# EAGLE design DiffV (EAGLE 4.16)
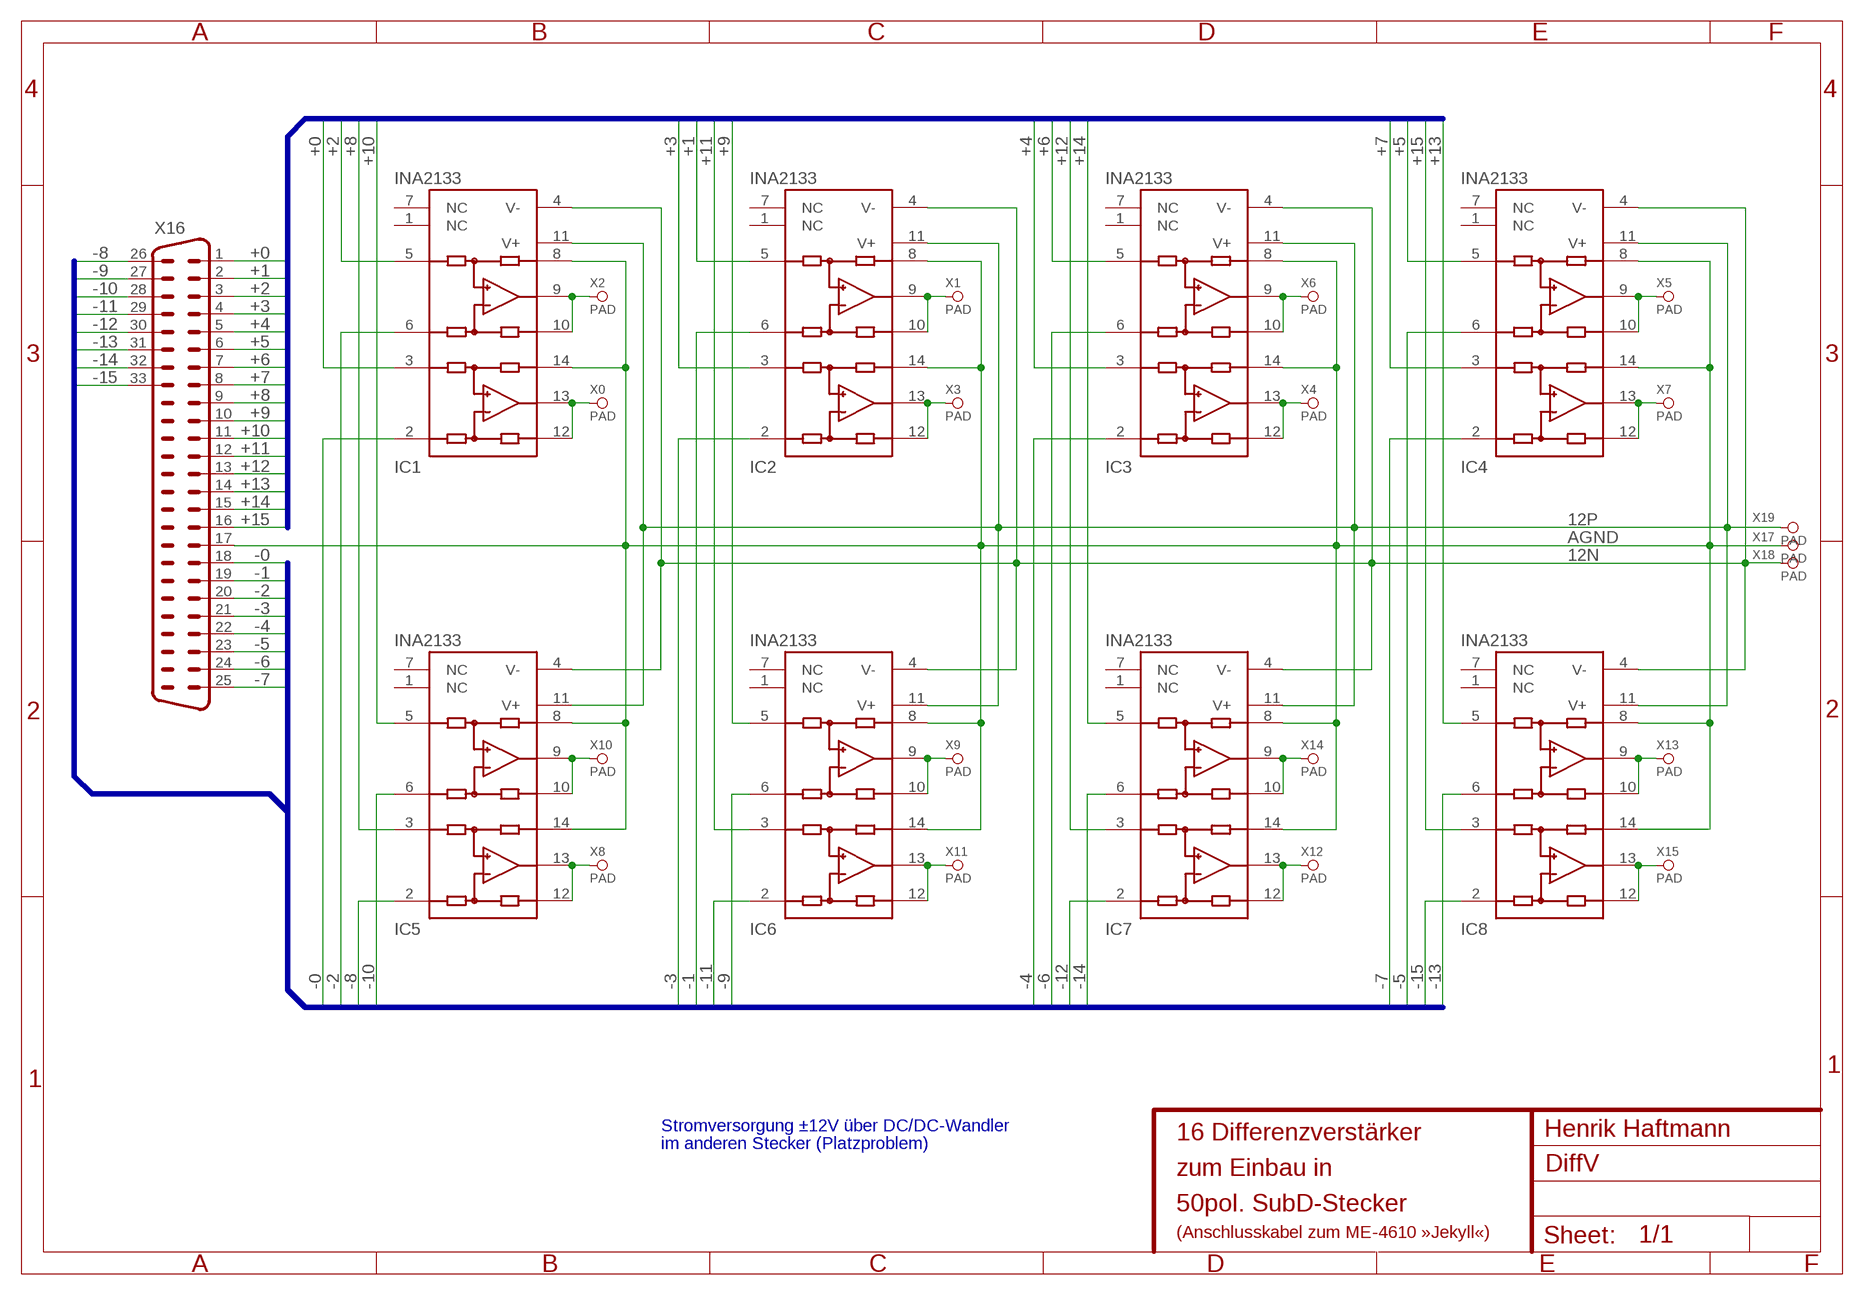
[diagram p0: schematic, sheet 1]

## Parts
IC1  INA2133  INA2134U  [SO14]
IC2  INA2133  INA2134U  [SO14]
IC3  INA2133  INA2134U  [SO14]
IC4  INA2133  INA2134U  [SO14]
IC5  INA2133  INA2134U  [SO14]
IC6  INA2133  INA2134U  [SO14]
IC7  INA2133  INA2134U  [SO14]
IC8  INA2133  INA2134U  [SO14]
X0  PAD  [PAD]
X1  PAD  [PAD]
X2  PAD  [PAD]
X3  PAD  [PAD]
X4  PAD  [PAD]
X5  PAD  [PAD]
X6  PAD  [PAD]
X7  PAD  [PAD]
X8  PAD  [PAD]
X9  PAD  [PAD]
X10  PAD  [PAD]
X11  PAD  [PAD]
X12  PAD  [PAD]
X13  PAD  [PAD]
X14  PAD  [PAD]
X15  PAD  [PAD]
X16  M50  [M50-33]
X17  PAD  [PAD]
X18  PAD  [PAD]
X19  PAD  [PAD]

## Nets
12N: IC1.4(V-) IC2.4(V-) IC3.4(V-) IC4.4(V-) IC5.4(V-) IC6.4(V-) IC7.4(V-) IC8.4(V-) X18.1
12P: IC1.11(V+) IC2.11(V+) IC3.11(V+) IC4.11(V+) IC5.11(V+) IC6.11(V+) IC7.11(V+) IC8.11(V+) X19.1
+0: IC1.3(+INA) X16.1
+1: IC2.5(+INB) X16.2
+2: IC1.5(+INB) X16.3
+3: IC2.3(+INA) X16.4
+4: IC3.3(+INA) X16.5
+5: IC4.5(+INB) X16.6
+6: IC3.5(+INB) X16.7
+7: IC4.3(+INA) X16.8
+8: IC5.3(+INA) X16.9
+9: IC6.5(+INB) X16.10
+10: IC5.5(+INB) X16.11
+11: IC6.3(+INA) X16.12
+12: IC7.3(+INA) X16.13
+13: IC8.5(+INB) X16.14
+14: IC7.5(+INB) X16.15
+15: IC8.3(+INA) X16.16
-0: IC1.2(-INA) X16.18
-1: IC2.6(-INB) X16.19
-2: IC1.6(-INB) X16.20
-3: IC2.2(-INA) X16.21
-4: IC3.2(-INA) X16.22
-5: IC4.6(-INB) X16.23
-6: IC3.6(-INB) X16.24
-7: IC4.2(-INA) X16.25
-8: IC5.2(-INA) X16.26
-9: IC6.6(-INB) X16.27
-10: IC5.6(-INB) X16.28
-11: IC6.2(-INA) X16.29
-12: IC7.2(-INA) X16.30
-13: IC8.6(-INB) X16.31
-14: IC7.6(-INB) X16.32
-15: IC8.2(-INA) X16.33
AGND: IC1.8(REFB) IC1.14(REFA) IC2.8(REFB) IC2.14(REFA) IC3.8(REFB) IC3.14(REFA) IC4.8(REFB) IC4.14(REFA) IC5.8(REFB) IC5.14(REFA) IC6.8(REFB) IC6.14(REFA) IC7.8(REFB) IC7.14(REFA) IC8.8(REFB) IC8.14(REFA) X16.17 X17.1
N$5: IC1.9(OUTB) IC1.10(SENSEB) X2.1
N$6: IC1.12(SENSEA) IC1.13(OUTA) X0.1
N$7: IC5.12(SENSEA) IC5.13(OUTA) X8.1
N$8: IC5.9(OUTB) IC5.10(SENSEB) X10.1
N$9: IC2.9(OUTB) IC2.10(SENSEB) X1.1
N$10: IC6.9(OUTB) IC6.10(SENSEB) X9.1
N$11: IC6.12(SENSEA) IC6.13(OUTA) X11.1
N$12: IC7.9(OUTB) IC7.10(SENSEB) X14.1
N$13: IC7.12(SENSEA) IC7.13(OUTA) X12.1
N$14: IC8.12(SENSEA) IC8.13(OUTA) X15.1
N$15: IC8.9(OUTB) IC8.10(SENSEB) X13.1
N$16: IC4.12(SENSEA) IC4.13(OUTA) X7.1
N$17: IC4.9(OUTB) IC4.10(SENSEB) X5.1
N$18: IC3.9(OUTB) IC3.10(SENSEB) X6.1
N$19: IC3.12(SENSEA) IC3.13(OUTA) X4.1
N$20: IC2.12(SENSEA) IC2.13(OUTA) X3.1
Unconnected: IC1.1(NC) IC1.7(NC) IC2.1(NC) IC2.7(NC) IC3.1(NC) IC3.7(NC) IC4.1(NC) IC4.7(NC) IC5.1(NC) IC5.7(NC) IC6.1(NC) IC6.7(NC) IC7.1(NC) IC7.7(NC) IC8.1(NC) IC8.7(NC)

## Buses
+[0..15]
-[0..15]

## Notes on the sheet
- Stromversorgung ±12V über DC/DC-Wandler
- 16 Differenzverstärker | Henrik Haftmann
- im anderen Stecker (Platzproblem)
- zum Einbau in
- 50pol. SubD-Stecker
- (Anschlusskabel zum ME-4610 »Jekyll«)

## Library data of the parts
IC1-IC8 = burr-brown:INA2134: Audio Differential Line Receivers 0dB, G=1
X0 X1-X15 X17-X19 = DiffV:PAD
X16 = DiffV:M50: SUB-D

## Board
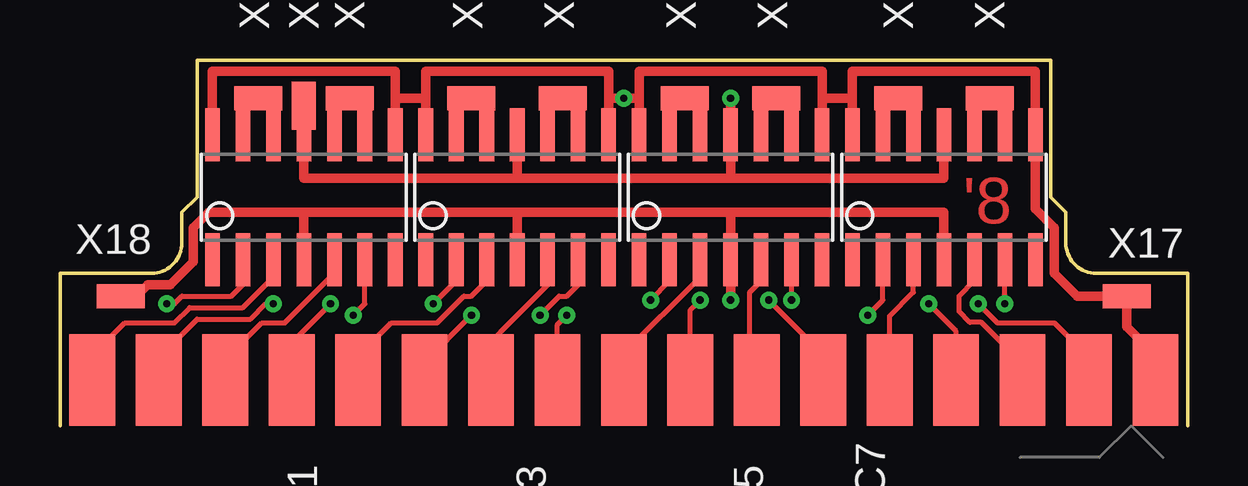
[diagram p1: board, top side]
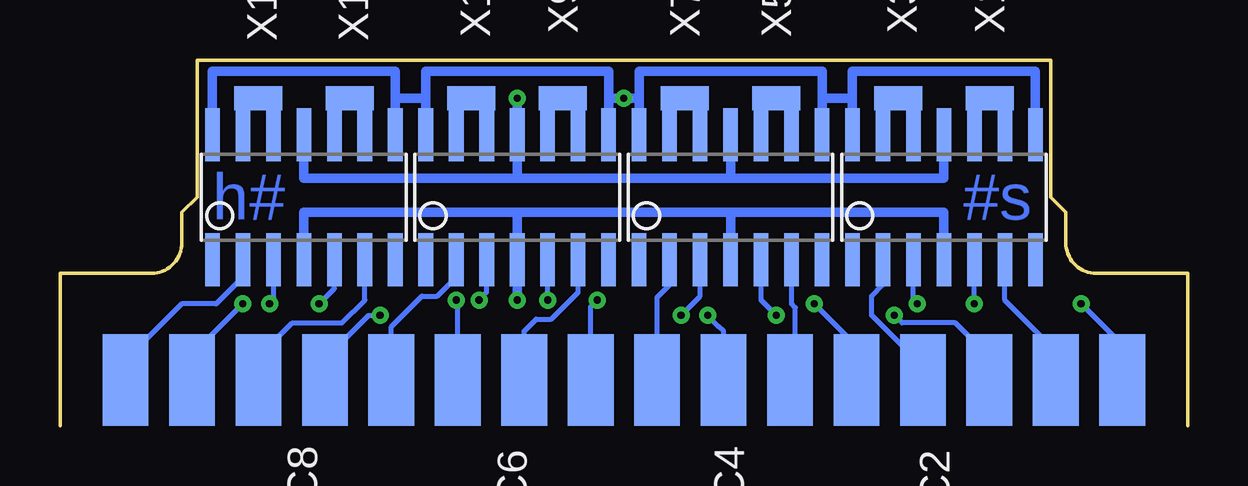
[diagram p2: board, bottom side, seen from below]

Size 46.99 x 15.24 mm. Coordinates in mm from the lower left corner, seen from the top.
Outline: 46.99,0 46.99,6.35 43.18,6.35 arc-90 41.91,7.62 41.91,8.89 41.27,9.53 41.27,15.24 5.71,15.24 5.71,9.53 5.08,8.89 5.08,7.62 arc-90 3.81,6.35 0,6.35 0,0
Copper layers (1*16): Top 0.035mm / dielectric 1.5mm / Bottom 0.035mm
Design rules "Felber": minimum track width 0.2mm, minimum drill 0.3mm, track to track 0.2mm, track to pad 0.2mm, pad to pad 0.2mm, via to via 0.2mm, smd to smd 0mil, copper to edge 0.2mm, drill to drill 0.3mm, minimum pad ring 10mil, minimum via ring 8mil, stop-mask expansion 4mil, vias tented up to drill 0.4mm, thermal gap 10mil

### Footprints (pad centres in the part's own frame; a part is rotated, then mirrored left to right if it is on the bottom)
SO14 = smd 0.61 x 2.21: 1 -3.81,-2.603; 2 -2.54,-2.603; 3 -1.27,-2.603; 4 0,-2.603; 5 1.27,-2.603; 6 2.54,-2.603; 7 3.81,-2.603; 8 3.81,2.603; 9 2.54,2.603; 10 1.27,2.603; 11 0,2.603; 12 -1.27,2.603; 13 -2.54,2.603; 14 -3.81,2.603
PAD = smd 1 x 2: 1 0,0
M50-33 = smd 1.905 x 3.81: 1 22.149,-1.905; 2 19.38,-1.905; 3 16.612,-1.905; 4 13.843,-1.905; 5 11.074,-1.905; 6 8.306,-1.905; 7 5.537,-1.905; 8 2.769,-1.905; 9 0,-1.905; 10 -2.769,-1.905; 11 -5.537,-1.905; 12 -8.306,-1.905; 13 -11.074,-1.905; 14 -13.843,-1.905; 15 -16.612,-1.905; 16 -19.38,-1.905; 17 -22.149,-1.905 | smd 1.905 x 3.81 bottom: 18 20.765,-1.905; 19 17.996,-1.905; 20 15.227,-1.905; 21 12.459,-1.905; 22 9.69,-1.905; 23 6.921,-1.905; 24 4.153,-1.905; 25 1.384,-1.905; 26 -1.384,-1.905; 27 -4.153,-1.905; 28 -6.921,-1.905; 29 -9.69,-1.905; 30 -12.459,-1.905; 31 -15.227,-1.905; 32 -17.996,-1.905; 33 -20.765,-1.905

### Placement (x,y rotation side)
IC1  10.16,9.53 0 top
IC2  10.16,9.53 0 bottom
IC3  19.05,9.53 0 top
IC4  19.05,9.53 0 bottom
IC5  27.94,9.53 0 top
IC6  27.94,9.53 0 bottom
IC7  36.83,9.53 0 top
IC8  36.83,9.53 0 bottom
X0  8.26,13.65 270 top
X1  8.26,13.65 90 bottom
X2  12.07,13.65 270 top
X3  12.07,13.65 90 bottom
X4  17.15,13.65 90 top
X5  17.15,13.65 90 bottom
X6  20.96,13.65 270 top
X7  20.96,13.65 90 bottom
X8  26.04,13.65 270 top
X9  26.03,13.65 270 bottom
X10  29.85,13.65 270 top
X11  29.85,13.65 90 bottom
X12  34.92,13.65 90 top
X13  34.92,13.65 90 bottom
X14  38.73,13.65 270 top
X15  38.73,13.65 90 bottom
X16  23.5,0 180 top
X17  44.45,5.4 270 top
X18  2.54,5.4 270 top
X19  10.16,13.34 0 top

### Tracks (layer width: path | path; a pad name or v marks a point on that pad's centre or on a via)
12N  (via drill 0.3)
  Top 0.4: IC8.4 36.83,8.89 27.94,8.89 | 27.94,8.89 IC6.4 v27.94,5.24 | 19.05,8.89 IC4.4 | 19.05,8.89 27.94,8.89 | 10.16,8.89 IC2.4 | 10.16,8.89 19.05,8.89 | X18.1 3.17,5.4 3.65,5.87 4.6,5.87 5.56,6.83 | 5.56,6.83 | 5.56,6.83 5.56,8.26 6.19,8.89 10.16,8.89
  Bottom 0.2: 27.94,6.99 IC6.4
  Bottom 0.4: IC2.4 10.16,8.89 19.05,8.89 | 19.05,8.89 IC4.4 | 27.94,8.89 27.94,6.99 v27.94,5.24 | 27.94,8.89 19.05,8.89 | IC8.4 36.83,8.89 27.94,8.89
12P  (via drill 0.3)
  Top 0.2: X19.1 | IC2.11 X19.1
  Top 0.4: 19.05,10.32 IC4.11 | 19.05,10.32 10.16,10.32 IC2.11 | 27.94,10.32 19.05,10.32 | 27.94,10.32 36.83,10.32 IC8.11 | v27.94,13.65 IC6.11 27.94,10.32
  Bottom 0.4: 19.05,10.32 IC4.11 | 19.05,10.32 10.16,10.32 IC2.11 | 19.05,10.32 27.94,10.32 | v27.94,13.65 IC6.11 27.94,10.32 | IC8.11 36.83,10.32 27.94,10.32
+0
  Top 0.2: IC1.3 8.89,6.19 7.62,4.92 5.4,4.92 4.76,4.29 2.7,4.29 1.35,2.93 X16.1
+1  (via drill 0.3)
  Top 0.2: v8.89,5.08 8.57,5.08 7.94,4.45 5.71,4.45 4.12,2.85 X16.2
  Bottom 0.2: v8.89,5.08 IC2.5
+2
  Top 0.2: X16.3 6.88,2.76 8.41,4.29 9.37,4.29 11.43,6.35 IC1.5
+3  (via drill 0.3)
  Top 0.2: X16.4 9.65,3.46 v11.27,5.08
  Bottom 0.2: IC2.3 11.43,5.24 v11.27,5.08
+4
  Top 0.2: IC3.3 17.78,6.03 17.15,5.4 16.83,5.4 15.72,4.29 13.81,4.29 12.61,3.09 12.42,2.9 X16.5
+5  (via drill 0.3)
  Top 0.2: X16.6 15.19,2.65 v17.15,4.6
  Bottom 0.2: v17.15,4.6 17.78,5.24 IC4.5
+6
  Top 0.2: 18.37,3.92 18.89,4.45 | 18.89,4.45 | 18.89,4.45 20.32,5.87 IC3.5 | 18.37,3.92 | X16.7 17.96,3.51 18.37,3.92
+7  (via drill 0.3)
  Top 0.2: v21.11,4.6 20.85,4.34 | v21.11,4.6 | X16.8 20.73,4.22 v21.11,4.6
  Bottom 0.2: v21.11,4.6 20.32,5.4 IC4.3
+8
  Top 0.2: X16.9 23.5,3.02 26.67,6.19 IC5.3
+9  (via drill 0.3)
  Top 0.2: X16.10 26.26,4.83 v26.67,5.24
  Bottom 0.2: v26.67,5.24 IC6.5
+10
  Top 0.2: IC5.5 29.21,6.03 28.73,5.56 28.73,3.17 29.03,2.88 X16.11
+11  (via drill 0.3)
  Top 0.2: X16.12 31.8,2.97 v29.53,5.24
  Bottom 0.2: v29.53,5.24 29.21,5.56 IC6.3
+12
  Top 0.2: IC7.3 35.56,5.56 34.57,4.57 X16.13
+13  (via drill 0.3)
  Top 0.2: X16.14 37.34,3.94 v36.2,5.08
  Bottom 0.2: v36.2,5.08 35.56,5.71 IC8.5
+14
  Top 0.2: IC7.5 38.1,6.03 37.46,5.4 37.46,4.76 37.92,4.31 38.39,4.31 40.11,2.6 X16.15
+15  (via drill 0.3)
  Top 0.2: 42.7,3.02 41.43,4.29 39.05,4.29 v38.26,5.08 | 42.7,3.02 42.78,2.94 | X16.16 42.88,2.85 42.7,3.02
  Bottom 0.2: v38.26,5.08 38.1,5.24 IC8.3 38.1,6.99
-0  (via drill 0.3)
  Top 0.2: v4.45,5.08 | v4.45,5.08 4.76,5.08 5.08,5.4 7.14,5.4 7.62,5.87 IC1.2
  Bottom 0.2: v4.45,5.08 3.05,3.68 2.73,3.37 X16.18
-1
  Bottom 0.2: IC2.6 7.62,5.24 6.33,3.94 | 6.33,3.94 | X16.19 5.5,3.12 6.33,3.94
-2  (via drill 0.3)
  Top 0.2: v12.22,4.6 | IC1.6 12.7,5.08 v12.22,4.6
  Bottom 0.2: 8.41,3.02 9.68,4.29 11.91,4.29 v12.22,4.6 | 8.41,3.02 8.33,2.93 | X16.20 8.27,2.87 8.41,3.02
-3
  Bottom 0.2: IC2.2 12.7,5.87 13.18,5.4 13.18,4.6 11.61,3.04 11.61,2.88 11.04,2.31 X16.21
-4  (via drill 0.3)
  Top 0.2: v15.56,5.08 16.51,6.03 IC3.2
  Bottom 0.2: 14.29,3.81 14.25,3.77 | 14.29,3.81 v15.56,5.08 | X16.22 13.8,3.33 14.29,3.81
-5
  Bottom 0.2: IC4.6 16.51,5.08 16.35,4.92 16.35,3.49 16.57,3.27 X16.23
-6  (via drill 0.3)
  Top 0.2: v20,4.6 20.8,5.4 21.11,5.4 21.59,5.87 IC3.6
  Bottom 0.2: v20,4.6 19.53,4.13 19.34,3.94 X16.24
-7
  Bottom 0.2: 21.59,5.87 IC4.2 | 21.59,5.87 | X16.25 22.11,5.35 21.59,5.87
-8  (via drill 0.3)
  Top 0.2: v24.61,5.24 25.4,6.03 IC5.2
  Bottom 0.2: v24.61,5.24 24.82,5.03 | v24.61,5.24 | X16.26 24.88,4.97 v24.61,5.24
-9
  Bottom 0.2: IC6.6 25.4,5.56 26.51,4.45 27.15,4.45 27.65,3.94 X16.27
-10  (via drill 0.3)
  Top 0.2: v30.48,5.24 IC5.6
  Bottom 0.2: X16.28 30.42,5.17 v30.48,5.24
-11
  Bottom 0.2: IC6.2 30.48,6.19 31.27,5.4 31.91,5.4 33.18,4.12 X16.29
-12  (via drill 0.3)
  Top 0.2: v33.66,4.6 34.29,5.24 IC7.2
  Bottom 0.2: v33.66,4.6 34.13,4.6 35.95,2.78 X16.30
-13
  Bottom 0.2: 38.58,3.02 37.31,4.29 35.24,4.29 34.29,5.24 IC8.6 | 38.58,3.02 38.66,2.93 | X16.31 38.72,2.87 38.58,3.02
-14  (via drill 0.3)
  Top 0.2: v39.37,5.08 IC7.6
  Bottom 0.2: v39.37,5.08 40.66,3.79 40.67,3.79 41.49,2.96 X16.32
-15
  Bottom 0.2: 44.1,2.89 41.91,5.08 40.48,5.08 39.37,6.19 IC8.2 | 44.1,2.89 | X16.33 44.26,2.73 44.1,2.89
AGND  (via drill 0.3)
  Top 0.2: IC7.14 33.02,12.06
  Top 0.4: 13.97,13.65 IC2.14 | 15.24,13.65 IC3.14 | 15.24,13.65 13.97,13.65 | 33.02,13.65 IC7.14 | 33.02,13.65 33.02,14.76 40.64,14.76 IC7.8 40.64,9.05 41.43,8.26 41.43,6.35 42.39,5.4 X17.1 44.45,4.13 45.64,2.93 X16.17 | 31.75,13.65 IC6.14 | 31.75,13.65 33.02,13.65 | 24.13,13.65 IC6.8 | 24.13,13.65 24.13,14.76 31.75,14.76 31.75,13.65 | 22.86,13.65 IC3.8 | 22.86,13.65 v23.5,13.65 24.13,13.65 | IC2.8 6.35,14.76 13.97,14.76 13.97,13.65 | 15.24,13.65 15.24,14.76 22.86,14.76 22.86,13.65
  Bottom 0.2: IC7.14 33.02,12.06
  Bottom 0.4: IC7.8 40.64,14.76 33.02,14.76 33.02,13.65 | 33.02,13.65 IC7.14 | 24.13,13.65 IC6.8 | 24.13,13.65 24.13,14.76 31.75,14.76 31.75,13.65 | 15.24,13.65 IC3.14 | 15.24,13.65 15.24,14.76 22.86,14.76 22.86,13.65 | 13.97,13.65 13.97,14.76 6.35,14.76 IC2.8 | 13.97,13.65 15.24,13.65 | 13.97,13.65 IC2.14 | 22.86,13.65 IC3.8 | 22.86,13.65 v23.5,13.65 24.13,13.65 | 31.75,13.65 IC6.14 | 31.75,13.65 33.02,13.65
N$5
  Top 0.2: IC1.9 12.7,13.65 X2.1 11.43,13.65 IC1.10
N$6
  Top 0.2: IC1.12 8.89,13.65 X0.1 7.62,13.65 IC1.13
N$7
  Top 0.2: IC5.13 25.4,13.65 X8.1 | X8.1 | IC5.12 26.67,13.65 X8.1
N$8
  Top 0.2: IC5.10 29.21,13.65 X10.1 | X10.1 | X10.1 | IC5.9 30.48,13.65 X10.1
N$9
  Bottom 0.2: IC2.9 7.62,13.65 X1.1 | X1.1 | IC2.10 8.89,13.65 X1.1
N$10
  Bottom 0.2: IC6.9 25.4,13.65 X9.1 26.67,13.65 IC6.10
N$11
  Bottom 0.2: IC6.12 29.21,13.65 X11.1 30.48,13.65 IC6.13
N$12
  Top 0.2: IC7.9 39.37,13.65 X14.1 | X14.1 | IC7.10 38.1,13.65 X14.1
N$13
  Top 0.2: IC7.12 35.56,13.65 X12.1 | X12.1 | IC7.13 34.29,13.65 X12.1
N$14
  Bottom 0.2: IC8.12 38.1,13.65 X15.1 39.37,13.65 IC8.13
N$15
  Bottom 0.2: IC8.9 34.29,13.65 X13.1 | X13.1 | IC8.10 35.56,13.65 X13.1
N$16
  Bottom 0.2: IC4.13 21.59,13.65 X7.1 20.32,13.65 IC4.12
N$17
  Bottom 0.2: IC4.9 16.51,13.65 X5.1 | X5.1 | X5.1 | IC4.10 17.78,13.65 X5.1
N$18
  Top 0.2: IC3.9 21.59,13.65 X6.1 20.32,13.65 IC3.10
N$19
  Top 0.2: IC3.13 16.51,13.65 16.99,13.65 X4.1 17.78,13.65 IC3.12
N$20
  Bottom 0.2: IC2.12 11.43,13.65 X3.1 | IC2.13 12.7,13.65 X3.1 | X3.1

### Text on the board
Top: '8
Bottom: #s | h#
